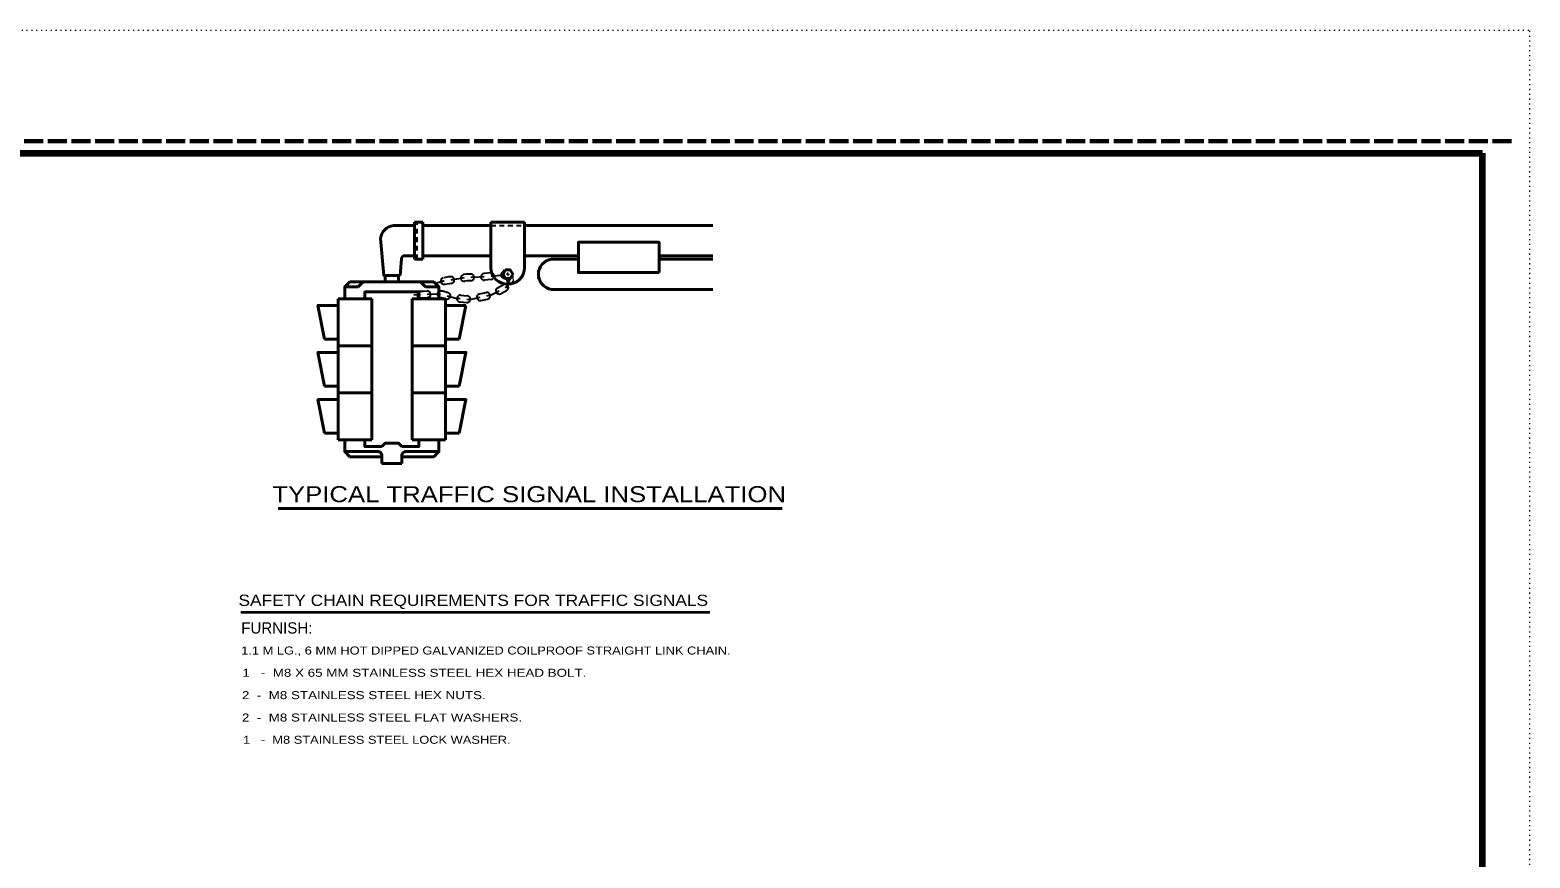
# Model space of a CAD drawing. Extents: x 312583 to 312854, y 144419 to 144597.
# Drawn here: x 312711 to 312853.5, y 144518.1 to 144596.8 of the extents above; entities that cross this region are included whole.
import ezdxf
from ezdxf.enums import TextEntityAlignment as Align

# ---------------------------------------------------------------- set-up
doc = ezdxf.new("R2010")
doc.units = 0
doc.header["$LTSCALE"] = 0.3
for name, pattern in [('DOTTED', [1.5, 0.3, -1.2]), ('LONG_DASHED', [7.5, 6, -1.5]), ('SHORT_DASHED', [2.7, 1.5, -1.2])]:
    doc.linetypes.add(name, pattern=pattern)
for name, color, linetype, lineweight in [('1', 7, 'Continuous', 40), ('2', 7, 'Continuous', 40), ('62', 7, 'DOTTED', 13), ('63', 7, 'LONG_DASHED', 60)]:
    doc.layers.add(name, color=color, linetype=linetype, lineweight=lineweight)

msp = doc.modelspace()

# ---------------------------------------------------------------- linework, layer by layer
at = {"layer": '1', "lineweight": 158}
msp.add_line((312849, 144423.1446), (312849, 144585.0846), dxfattribs=at)
at = {"layer": '1', "lineweight": 106}
msp.add_line((312849, 144423.1446), (312849, 144584.0756), dxfattribs=at)
at = {"layer": '1'}
for p, q in [((312747.532, 144578.2156), (312745.531, 144578.2156)), ((312747.532, 144575.0263), (312747.532, 144578.5376)), ((312748.3294, 144578.5376), (312747.532, 144578.5376)), ((312748.3294, 144575.0263), (312748.3294, 144578.5376)), ((312754.7924, 144578.2156), (312748.3294, 144578.2156)), ((312754.7924, 144574.229), (312754.7924, 144578.5376)), ((312754.7924, 144578.5376), (312757.9894, 144578.5376)), ((312757.9894, 144574.229), (312757.9894, 144578.5376)), ((312757.9894, 144578.2156), (312775.8757, 144578.2156)), ((312746.2977, 144575.0493), (312746.1597, 144573.4776)), ((312747.532, 144575.3406), (312746.6197, 144575.3406)), ((312754.7924, 144575.3406), (312748.3294, 144575.3406)), ((312757.9894, 144575.3406), (312763.103, 144575.3406)), ((312770.7697, 144575.3406), (312775.8757, 144575.3406)), ((312748.3294, 144575.0263), (312747.532, 144575.0263)), ((312760.5424, 144575.0263), (312763.103, 144575.0263)), ((312770.7697, 144575.0263), (312775.8757, 144575.0263)), ((312740.908, 144571.262), (312740.908, 144572.3813)), ((312741.391, 144572.8643), (312745.3854, 144572.8643)), ((312742.6637, 144572.8643), (312742.1884, 144572.3813)), ((312744.7414, 144572.8643), (312744.7414, 144573.4776)), ((312749.372, 144572.8643), (312745.3854, 144572.8643)), ((312746.0217, 144573.4776), (312746.0217, 144572.8643)), ((312748.0994, 144572.8643), (312748.5747, 144572.3813)), ((312749.855, 144571.262), (312749.855, 144572.3813)), ((312743.4687, 144571.262), (312740.2717, 144571.262)), ((312740.2717, 144566.7923), (312740.2717, 144571.262)), ((312743.4687, 144566.7923), (312743.4687, 144571.262)), ((312747.302, 144571.262), (312750.4914, 144571.262)), ((312747.302, 144566.7923), (312747.302, 144571.262)), ((312750.4914, 144566.7923), (312750.4914, 144571.262)), ((312760.5424, 144572.1513), (312775.8757, 144572.1513)), ((312750.4914, 144570.6256), (312752.408, 144570.6256)), ((312752.408, 144570.6256), (312751.7717, 144567.4286)), ((312740.2717, 144567.4286), (312738.9914, 144567.4286)), ((312743.4687, 144566.7923), (312740.2717, 144566.7923)), ((312740.2717, 144562.3226), (312740.2717, 144566.7923)), ((312743.4687, 144562.3226), (312743.4687, 144566.7923)), ((312747.302, 144566.7923), (312750.4914, 144566.7923)), ((312747.302, 144562.3226), (312747.302, 144566.7923)), ((312750.4914, 144567.4286), (312751.7717, 144567.4286)), ((312750.4914, 144562.3226), (312750.4914, 144566.7923)), ((312740.2717, 144562.959), (312738.9914, 144562.959)), ((312740.2717, 144557.8453), (312740.2717, 144562.3226)), ((312750.4914, 144562.959), (312751.7717, 144562.959)), ((312750.4914, 144557.8453), (312750.4914, 144562.3226)), ((312740.2717, 144558.4893), (312738.9914, 144558.4893)), ((312750.4914, 144558.4893), (312751.7717, 144558.4893)), ((312743.4687, 144557.8453), (312740.2717, 144557.8453)), ((312740.908, 144557.8453), (312740.908, 144556.7336)), ((312747.302, 144557.8453), (312750.4914, 144557.8453)), ((312749.855, 144557.8453), (312749.855, 144556.7336)), ((312741.391, 144556.2506), (312744.427, 144556.2506)), ((312744.427, 144556.4116), (312744.427, 144555.6143)), ((312744.427, 144555.6143), (312745.3854, 144555.6143)), ((312746.3437, 144555.6143), (312745.3854, 144555.6143)), ((312746.3437, 144556.4116), (312746.3437, 144555.6143)), ((312749.372, 144556.2506), (312746.3437, 144556.2506))]:
    msp.add_line(p, q, dxfattribs=at)
at = {"layer": '1', "linetype": 'SHORT_DASHED', "lineweight": 25}
for p, q in [((312747.7697, 144575.0263), (312747.7697, 144578.5376)), ((312754.7924, 144578.2156), (312757.9894, 144578.2156))]:
    msp.add_line(p, q, dxfattribs=at)
at = {"layer": '1', "lineweight": 158}
msp.add_lwpolyline([(312616.5, 144423.1446), (312616.5, 144585.0846), (312849, 144585.0846)], dxfattribs=at)
at = {"layer": '1'}
for points in [[(312744.2967, 144576.9813), (312744.6034, 144573.4776), (312746.1597, 144573.4776)], [(312741.391, 144572.8643), (312740.908, 144572.3813), (312742.1884, 144572.3813)], [(312749.372, 144572.8643), (312749.855, 144572.3813), (312748.5747, 144572.3813)], [(312742.8247, 144571.262), (312742.8247, 144571.906), (312745.3854, 144571.906)], [(312747.9384, 144571.262), (312747.9384, 144571.906), (312745.3854, 144571.906)], [(312740.2717, 144570.6256), (312738.355, 144570.6256), (312738.9914, 144567.4286)], [(312740.2717, 144566.156), (312738.355, 144566.156), (312738.9914, 144562.959)], [(312750.4914, 144566.156), (312752.408, 144566.156), (312751.7717, 144562.959)], [(312743.4687, 144557.8453), (312743.4687, 144562.3226), (312740.2717, 144562.3226)], [(312747.302, 144557.8453), (312747.302, 144562.3226), (312750.4914, 144562.3226)], [(312740.2717, 144561.6786), (312738.355, 144561.6786), (312738.9914, 144558.4893)], [(312750.4914, 144561.6786), (312752.408, 144561.6786), (312751.7717, 144558.4893)], [(312741.391, 144556.2506), (312740.908, 144556.7336), (312744.105, 144556.7336)], [(312742.8247, 144557.8453), (312742.8247, 144557.209), (312744.427, 144557.209)], [(312744.427, 144557.209), (312744.7414, 144557.531), (312745.3854, 144557.531)], [(312746.3437, 144557.209), (312746.0217, 144557.531), (312745.3854, 144557.531)], [(312747.9384, 144557.8453), (312747.9384, 144557.209), (312746.3437, 144557.209)], [(312749.372, 144556.2506), (312749.855, 144556.7336), (312746.658, 144556.7336)]]:
    msp.add_lwpolyline(points, dxfattribs=at)
for points in [[(312770.7697, 144573.746), (312763.103, 144573.746), (312763.103, 144576.621), (312770.7697, 144576.621)], [(312756.1494, 144573.999), (312756.6324, 144573.999), (312756.87, 144573.585), (312756.6324, 144573.171), (312756.157, 144573.171), (312755.9117, 144573.585)]]:
    msp.add_lwpolyline(points, close=True, dxfattribs=at)
for centre, radius, start, end in [((312745.7342, 144576.782), 1.4518, 98.04577, 171.95566), ((312746.6158, 144575.025), 0.3194, 90, 175.00686), ((312756.3921, 144574.2264), 1.5972, 180, 0), ((312760.7481, 144573.5875), 1.4518, 98.04578, 261.95423), ((312744.1038, 144556.4116), 0.3194, 0, 90), ((312746.6593, 144556.4116), 0.3194, 90, 180)]:
    msp.add_arc(centre, radius, start, end, dxfattribs=at)
at = {"layer": '2', "lineweight": 25}
for p, q in [((312754.7694, 144573.7076), (312754.133, 144573.654)), ((312752.247, 144573.2323), (312750.9897, 144573.033)), ((312754.823, 144573.0713), (312754.1867, 144573.0176)), ((312755.421, 144572.3046), (312755.9884, 144572.596)), ((312747.463, 144571.63), (312748.107, 144571.653)), ((312751.856, 144570.9553), (312752.4924, 144570.9016)), ((312751.9097, 144571.5916), (312752.546, 144571.538)), ((312753.7037, 144571.7143), (312754.3247, 144571.8523)), ((312753.8417, 144571.0856), (312754.4627, 144571.2236)), ((312755.7124, 144571.7373), (312756.2797, 144572.0286))]:
    msp.add_line(p, q, dxfattribs=at)
at = {"layer": '2', "lineweight": 13}
for p, q in [((312756.3947, 144573.585), (312756.3947, 144573.7613)), ((312756.3947, 144573.585), (312756.226, 144573.585)), ((312756.3947, 144573.585), (312756.5634, 144573.585)), ((312756.3947, 144573.585), (312756.3947, 144573.4163)), ((312756.9314, 144572.941), (312756.87, 144573.5696))]:
    msp.add_line(p, q, dxfattribs=at)
at = {"layer": '2'}
msp.add_line((312734.5942, 144551.3309), (312782.4721, 144551.3309), dxfattribs=at)
at = {"layer": '2', "lineweight": 35}
msp.add_line((312731.0289, 144541.477), (312775.5887, 144541.477), dxfattribs=at)
at = {"layer": '2', "lineweight": 25}
for points in [[(312750.3534, 144572.9333), (312750.246, 144572.918), (312749.5407, 144572.6956)], [(312750.936, 144573.3473), (312750.752, 144573.3243), (312750.3074, 144573.2476)], [(312751.0357, 144572.7186), (312750.8517, 144572.688), (312750.407, 144572.619)], [(312752.8757, 144573.6003), (312752.477, 144573.5926), (312752.201, 144573.5466)], [(312752.891, 144572.9563), (312752.5307, 144572.9486), (312752.3007, 144572.918)], [(312754.1637, 144573.3396), (312753.673, 144573.3013), (312752.8834, 144573.2783)], [(312755.9884, 144573.5083), (312755.9577, 144573.5083), (312755.1144, 144573.4163), (312754.8, 144573.3933)], [(312756.134, 144572.3123), (312756.341, 144572.4196), (312756.6937, 144573.3013), (312756.7014, 144573.2936)], [(312748.0917, 144571.9673), (312748.36, 144571.975), (312748.7204, 144571.998)], [(312748.1147, 144571.331), (312748.3907, 144571.3386), (312748.7664, 144571.3616)], [(312748.7434, 144571.6836), (312749.3107, 144571.7143), (312750.016, 144571.6913)], [(312750.0084, 144571.377), (312750.108, 144571.3693), (312750.545, 144571.239)], [(312750.0314, 144572.0133), (312750.2154, 144572.0056), (312750.729, 144571.8523)], [(312750.637, 144571.5456), (312751.4497, 144571.308), (312751.879, 144571.2696)], [(312752.5154, 144571.216), (312752.8297, 144571.193), (312753.7727, 144571.4)], [(312754.3937, 144571.538), (312754.8154, 144571.63), (312755.5667, 144572.021)]]:
    msp.add_lwpolyline(points, dxfattribs=at)
for centre, start, end in [((312754.1608, 144573.3398), 94.68341, 274.68341), ((312754.7975, 144573.3919), 274.68341, 94.68341), ((312756.0691, 144573.517), 95.92378, 275.92378), ((312750.3516, 144572.9519), 107.57985, 287.57985), ((312750.9864, 144573.0356), 278.80442, 98.80442), ((312752.2491, 144573.2312), 98.80442, 278.80442), ((312752.8849, 144573.2802), 271.43678, 91.43678), ((312755.5657, 144572.0195), 117.44264, 297.44264), ((312756.1327, 144572.314), 297.44264, 117.44264), ((312756.6175, 144573.0391), 158.18421, 338.18421), ((312748.1042, 144571.651), 91.7723, 271.7723), ((312748.7422, 144571.6825), 273.59093, 93.59093), ((312750.0184, 144571.6937), 88.01913, 268.01913), ((312750.6369, 144571.548), 253.54592, 73.54592), ((312751.8784, 144571.2717), 85.17032, 265.17033), ((312752.5151, 144571.2179), 265.17032, 85.17032), ((312753.769, 144571.3998), 102.44317, 282.44317), ((312754.3929, 144571.5375), 282.44317, 102.44317)]:
    msp.add_arc(centre, 0.3194, start, end, dxfattribs=at)
at = {"layer": '62'}
msp.add_line((312601.2, 144596.7846), (312853.5, 144596.7846), dxfattribs=at)
msp.add_lwpolyline([(312601.2, 144418.5846), (312853.5, 144418.5846), (312853.5, 144596.7846)], dxfattribs=at)
at = {"layer": '63'}
msp.add_line((312851.75, 144586.2246), (312583.526, 144586.2246), dxfattribs=at)

# ---------------------------------------------------------------- texts
at = {"layer": '2'}
for s, height, width, p in [('TYPICAL TRAFFIC SIGNAL INSTALLATION ', 1.52, 1.2, (312758.7639, 144551.935)), ('SAFETY CHAIN REQUIREMENTS FOR TRAFFIC SIGNALS', 1.07, 1.15, (312753.1153, 144542.0794))]:
    msp.add_text(s, height=height, dxfattribs=dict(at, width=width)).set_placement(p, align=Align.CENTER)
msp.add_text('FURNISH:', height=1.07, dxfattribs=at).set_placement((312734.4521, 144539.4567), align=Align.CENTER)
for s, width, p in [('1.1 M LG., 6 MM HOT DIPPED GALVANIZED COILPROOF STRAIGHT LINK CHAIN.', 1.2, (312731.0709, 144537.4663)), ('1   -  M8 X 65 MM STAINLESS STEEL HEX HEAD BOLT.', 1.25, (312731.1726, 144535.3503)), ('2  -  M8 STAINLESS STEEL HEX NUTS.', 1.25, (312731.1407, 144533.2266)), ('2  -  M8 STAINLESS STEEL FLAT WASHERS.', 1.25, (312731.1407, 144531.103)), ('1   -  M8 STAINLESS STEEL LOCK WASHER.', 1.2, (312731.248, 144528.987))]:
    msp.add_text(s, height=0.76, dxfattribs=dict(at, width=width)).set_placement(p)

doc.saveas('drawing.dxf')
